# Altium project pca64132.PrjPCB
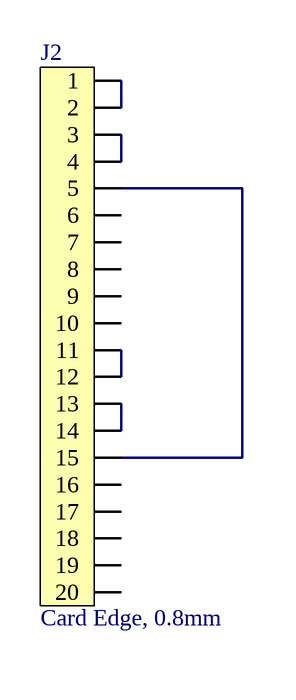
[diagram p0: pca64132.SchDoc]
SurfaceFinish: ENIG Gold; SoldermaskColor: Blue; SilkscreenColor: White; Revision: 0.2.0; ProjectNumber: 4456; ProjectName: nRF52 Desktop; PCBStackup: 2004; PCBRevision: 0018MASI; PCBNumber: 400398; PCAName: PCA64132; Organization: Nordic Semiconductor; NrOfLayers: 2; BoardTitle: nRF52 Desktop Debug Bypass Board; BoardThickness: 1.0mm; Author: RUBR
1 sheet, 1 parts. Net scope: global (net labels, ports and power ports of the same name join across sheets).
Board file: 400398.PcbDoc

## Sheet pca64132.SchDoc: =BoardTitle
size A4; Organization: Nordic Semiconductor; Revision: 0.2.0; SheetNumber: 1; SheetTotal: 1; Author: RUBR; CompanyName: Nordic Semiconductor; DrawnBy: RUBR

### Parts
J2  Card Edge, 0.8mm  [10056847-101LF Mating Board]

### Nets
NetJ2_1: J2.1 J2.2
NetJ2_3: J2.3 J2.4
NetJ2_5: J2.5 J2.15
NetJ2_11: J2.11 J2.12
NetJ2_13: J2.13 J2.14

Not connected (* = marked no-connect by the designer): J2 6 7 8 9 10 16 17 18 19 20

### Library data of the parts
J2 = 10056847-101LF Mating Board: 0.8mm pitch, dual edge, card edge connector; Artikkelnr Noca: N.A.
